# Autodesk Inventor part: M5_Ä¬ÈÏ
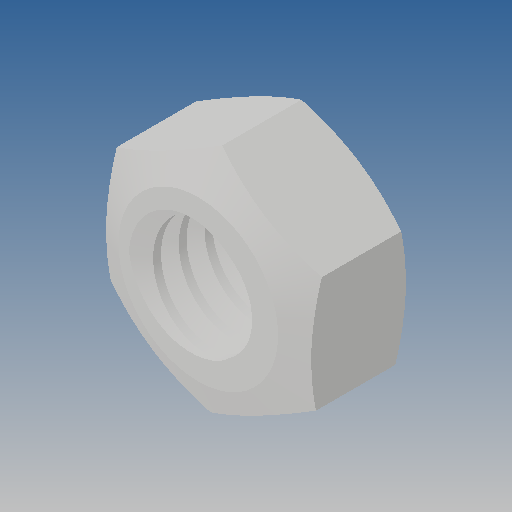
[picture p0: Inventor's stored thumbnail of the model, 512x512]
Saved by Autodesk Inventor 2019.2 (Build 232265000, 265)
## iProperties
Created: 2010-06
Part Number: M5_Ä¬ÈÏ
Material: Ogólny
Document SubType Name: Modeling
Designer: CADENGINEERING4
Density: 1 g/cm^3
Appearance: Domyślna
Author: CADENGINEERING4
Revision Number: ÈÎºÎ
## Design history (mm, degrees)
feature "NONE"
node "Bryła1"
